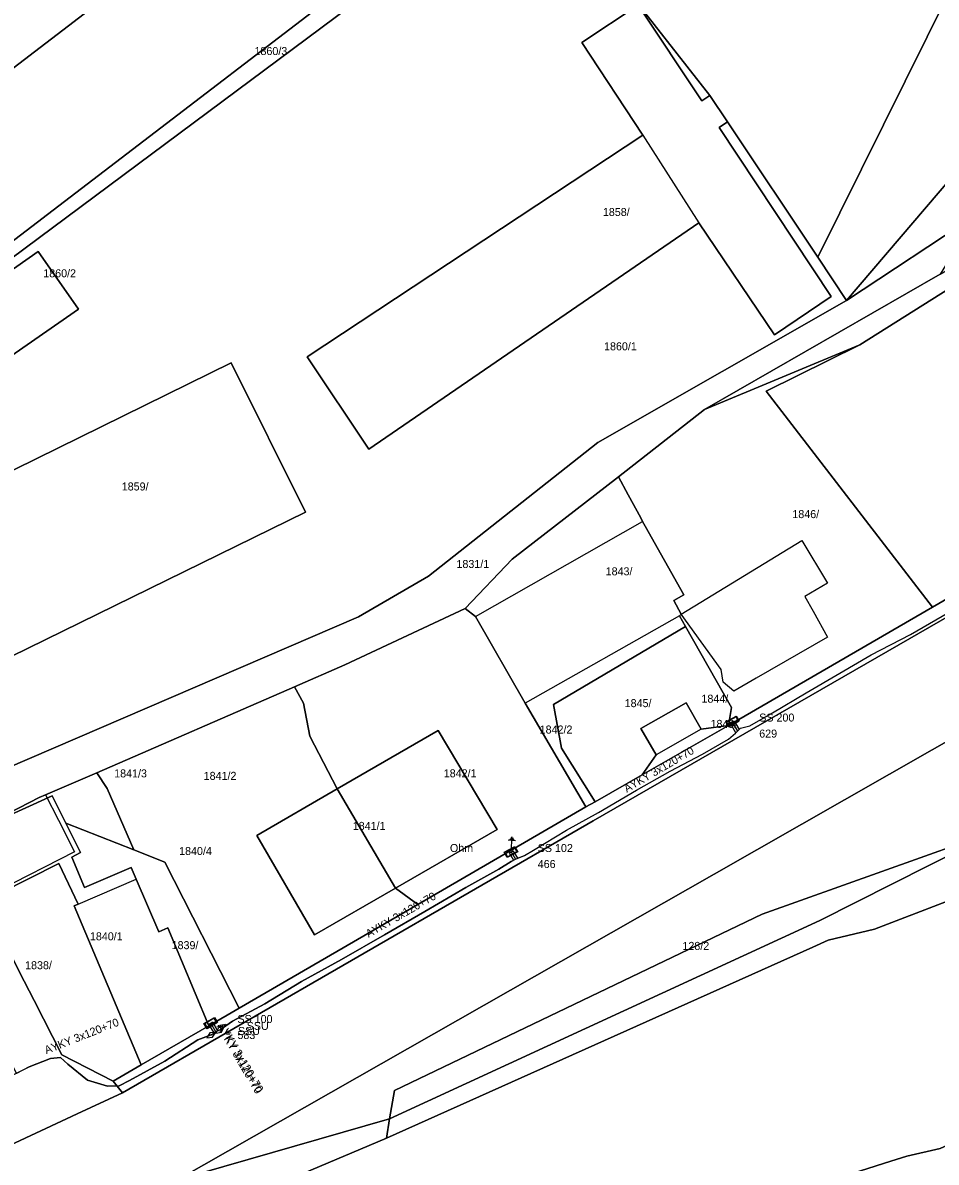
# Model space of a CAD drawing. Extents: x -793400 to -756198, y -1074141 to -1042963.
# Drawn here: x -783672.6 to -783587.1, y -1065150.4 to -1065043.7 of the extents above; entities that cross this region are included whole.
import ezdxf

# ---------------------------------------------------------------- set-up
doc = ezdxf.new("R2010")
doc.units = 0
for name, color, linetype in [('Parcela', 7, 'Continuous'), ('Popiskový text - Parcela', 7, 'Continuous'), ('Popiskový text - Přípojková skříň nn - SJZ', 7, 'Continuous'), ('Popiskový text - Přípojková skříň nn - Typ', 7, 'Continuous'), ('Popiskový text - Spojka nn - Typ', 7, 'Continuous'), ('Popiskový text - Uzemnění - Odpor', 7, 'Continuous'), ('Popiskový text - Vedení nn kabelové', 7, 'Continuous'), ('Skříň', 7, 'Continuous'), ('Spojka nn', 7, 'Continuous'), ('Spojnice nn', 7, 'Continuous'), ('Stavební objekt', 7, 'Continuous'), ('Uzemnění', 7, 'Continuous'), ('Vedení nn kabelové', 7, 'Continuous')]:
    doc.layers.add(name, color=color, linetype=linetype)

msp = doc.modelspace()

# ---------------------------------------------------------------- linework, layer by layer
at = {"layer": 'Parcela'}
for points in [[(-783679.68, -1065165.57), (-783638.54, -1065148.19), (-783598.62, -1065130.29), (-783597.17, -1065129.64), (-783592.85, -1065128.61), (-783579.36, -1065123.41), (-783559.97, -1065115.54), (-783529.78, -1065097.96), (-783514.83, -1065080.59), (-783511.59, -1065076.83), (-783504.59, -1065066.42), (-783502.44, -1065059.14), (-783500.79, -1065053.34), (-783499.02, -1065044.63), (-783497.17, -1065032.71), (-783496.04, -1065023.77), (-783495.21, -1065016.12), (-783492.53, -1064987.86), (-783488.71, -1064964.21), (-783486.09, -1064952.5), (-783482.83, -1064940.99), (-783478.28, -1064929.62)], [(-783478.28, -1064929.62), (-783482.83, -1064940.99), (-783486.09, -1064952.5), (-783488.71, -1064964.21), (-783492.53, -1064987.86), (-783497.09, -1065007.24), (-783502.14, -1065032.55), (-783506.35, -1065048.95), (-783511.77, -1065063.08), (-783521.44, -1065073.34), (-783546.39, -1065088.37), (-783607.85, -1065123.43), (-783658.1, -1065152.09), (-783678.31, -1065163.62)], [(-783676.21, -1065149.95), (-783668.48, -1065146.36), (-783667.48, -1065145.9), (-783663.26, -1065143.94), (-783619.19, -1065118.45), (-783559.07, -1065083.82), (-783559.84, -1065082.45), (-783540.15, -1065071.29), (-783534.17, -1065067.9), (-783529.45, -1065065.23), (-783521.94, -1065058.84), (-783520.86, -1065057.92), (-783514.53, -1065031.25), (-783497.32, -1064954.63), (-783495.09, -1064947.27), (-783490, -1064932.55)], [(-783461.55, -1064937.01), (-783469.34, -1064952.28), (-783475.47, -1064981.45), (-783479.58, -1065017.78), (-783482.56, -1065054.25), (-783487.35, -1065074.33), (-783494.31, -1065088.74), (-783495.21, -1065089.71), (-783498.48, -1065093.26), (-783502.16, -1065097.24), (-783520.29, -1065114.03), (-783532.97, -1065123.26), (-783564.78, -1065139.29), (-783586.68, -1065149.16), (-783589.8, -1065149.85), (-783591.32, -1065150.33), (-783630.75, -1065162.93), (-783655.71, -1065172.17), (-783680.17, -1065182.98)], [(-783680.17, -1065182.98), (-783655.71, -1065172.17), (-783630.75, -1065162.93), (-783591.32, -1065150.33), (-783589.8, -1065149.85), (-783586.68, -1065149.16), (-783564.78, -1065139.29), (-783532.97, -1065123.26), (-783520.29, -1065114.03), (-783502.16, -1065097.24), (-783498.48, -1065093.26), (-783495.21, -1065089.71), (-783494.31, -1065088.74), (-783487.35, -1065074.33), (-783482.56, -1065054.25), (-783479.58, -1065017.78), (-783475.47, -1064981.45), (-783469.34, -1064952.28), (-783461.55, -1064937.01)], [(-783497.17, -1065032.71), (-783499.02, -1065044.63), (-783500.79, -1065053.34), (-783502.44, -1065059.14), (-783504.59, -1065066.42), (-783512.37, -1065073.74), (-783513.55, -1065075.3), (-783516.49, -1065079.31), (-783531.67, -1065094.68), (-783561.96, -1065112.08), (-783580.95, -1065119.21), (-783603.34, -1065127.19), (-783637.77, -1065143.7), (-783638.24, -1065146.37), (-783658.1, -1065152.09), (-783607.85, -1065123.43), (-783546.39, -1065088.37), (-783521.44, -1065073.34), (-783511.77, -1065063.08), (-783506.35, -1065048.95), (-783502.14, -1065032.55)], [(-783680.77, -1065116.4), (-783641.16, -1065099.33), (-783634.61, -1065095.52), (-783618.75, -1065083), (-783595.45, -1065069.7), (-783583.27, -1065061.66), (-783586.7, -1065067.25), (-783608.77, -1065079.92), (-783616.82, -1065086.21), (-783626.75, -1065093.93), (-783631.18, -1065098.55), (-783642.42, -1065103.85), (-783647.16, -1065105.91), (-783665.66, -1065113.94), (-783670.46, -1065116.02), (-783671.05, -1065116.27), (-783677.6, -1065119.63)]]:
    msp.add_lwpolyline(points, dxfattribs=at)
for points in [[(-783679.72, -1065068.87), (-783696.3, -1065082.59), (-783703.49, -1065067.95), (-783701.82, -1065066.6), (-783693.07, -1065059.53), (-783681.16, -1065034.03), (-783688.84, -1065024.56), (-783667.93, -1064997.88), (-783659.12, -1064988.88), (-783657.73, -1064987.44), (-783656.18, -1064989.41), (-783657.28, -1064990.53), (-783648.71, -1064998.93), (-783633.99, -1065017.67), (-783634.29, -1065017.9), (-783683.34, -1065055.48), (-783678.2, -1065062.3), (-783682.41, -1065065.47)], [(-783594.2, -1065073.85), (-783608.77, -1065079.92), (-783586.7, -1065067.25), (-783573.68, -1065059.58), (-783565.81, -1065041.46), (-783556.5, -1065031.75), (-783555.01, -1065019.55), (-783544.22, -1064989.94), (-783545.48, -1065011.72), (-783554.46, -1065031.61), (-783557.75, -1065043.78), (-783560.55, -1065049.48), (-783561.45, -1065051.31), (-783563.64, -1065054.8), (-783565.28, -1065056.42), (-783566.79, -1065057.9), (-783570.36, -1065060.29), (-783572.51, -1065061.34), (-783577.12, -1065063.08)], [(-783575.44, -1065003.73), (-783565.51, -1065017.86), (-783567.73, -1065031.83), (-783572.73, -1065039.92), (-783583.05, -1065055.14), (-783595.45, -1065069.7), (-783598.14, -1065065.66), (-783579.73, -1065028.49), (-783592.56, -1065011.81), (-783602.84, -1065017.41), (-783606.12, -1065012.66), (-783597.36, -1065006.04), (-783592.12, -1065001.98), (-783590.3, -1065000.59)], [(-783579.73, -1065028.49), (-783598.14, -1065065.66), (-783606.59, -1065052.98), (-783608.24, -1065050.49), (-783624.81, -1065029.37), (-783602.84, -1065017.41), (-783592.56, -1065011.81)], [(-783626.47, -1065028.12), (-783679.72, -1065068.87), (-783682.41, -1065065.47), (-783678.2, -1065062.3), (-783683.34, -1065055.48), (-783634.29, -1065017.9), (-783633.99, -1065017.67), (-783626.05, -1065027.79)], [(-783583.27, -1065061.66), (-783595.45, -1065069.7), (-783583.05, -1065055.14), (-783572.73, -1065039.92), (-783567.73, -1065031.83), (-783565.51, -1065017.86), (-783562.68, -1065021.88), (-783563.99, -1065030.67), (-783581.17, -1065058.24)], [(-783624.81, -1065029.37), (-783696.3, -1065082.59), (-783679.72, -1065068.87), (-783626.47, -1065028.12), (-783626.05, -1065027.79)], [(-783624.81, -1065029.37), (-783608.24, -1065050.49), (-783609.02, -1065051.01), (-783614.97, -1065042.05), (-783620.25, -1065045.55), (-783614.53, -1065054.22), (-783645.96, -1065074.99), (-783640.19, -1065083.64), (-783609.28, -1065062.42), (-783602.2, -1065072.93), (-783596.89, -1065069.32), (-783607.37, -1065053.5), (-783606.59, -1065052.98), (-783598.14, -1065065.66), (-783595.45, -1065069.7), (-783618.75, -1065083), (-783634.61, -1065095.52), (-783641.16, -1065099.33), (-783680.77, -1065116.4), (-783687.19, -1065102.12), (-783688.13, -1065100.02), (-783693.78, -1065087.45), (-783696.3, -1065082.59)], [(-783614.97, -1065042.05), (-783609.02, -1065051.01), (-783608.24, -1065050.49), (-783606.59, -1065052.98), (-783607.37, -1065053.5), (-783596.89, -1065069.32), (-783602.2, -1065072.93), (-783609.28, -1065062.42), (-783640.19, -1065083.64), (-783645.96, -1065074.99), (-783614.53, -1065054.22), (-783620.25, -1065045.55)], [(-783559.84, -1065082.45), (-783587.42, -1065098.44), (-783602.99, -1065078.19), (-783594.2, -1065073.85), (-783577.12, -1065063.08), (-783572.51, -1065061.34)], [(-783667.38, -1065070.51), (-783671.15, -1065065.12), (-783678.96, -1065070.57), (-783675.18, -1065075.93)], [(-783667.38, -1065070.51), (-783675.18, -1065075.93), (-783678.96, -1065070.57), (-783671.15, -1065065.12)], [(-783598.62, -1065130.29), (-783638.54, -1065148.19), (-783638.24, -1065146.37), (-783597.95, -1065127.79), (-783580.95, -1065119.21), (-783561.96, -1065112.08), (-783531.67, -1065094.68), (-783516.49, -1065079.31), (-783513.55, -1065075.3), (-783512.37, -1065073.74), (-783504.59, -1065066.42), (-783511.59, -1065076.83), (-783514.83, -1065080.59), (-783529.78, -1065097.96), (-783559.97, -1065115.54), (-783579.36, -1065123.41), (-783592.85, -1065128.61), (-783597.17, -1065129.64)], [(-783587.42, -1065098.44), (-783606.5, -1065109.51), (-783606.24, -1065107.84), (-783610.53, -1065100.23), (-783611.09, -1065099.25), (-783610.93, -1065099.1), (-783611.64, -1065097.81), (-783610.68, -1065097.28), (-783614.3, -1065090.84), (-783614.55, -1065090.41), (-783614.73, -1065090.07), (-783615.91, -1065087.92), (-783616.82, -1065086.21), (-783608.77, -1065079.92), (-783594.2, -1065073.85), (-783602.99, -1065078.19)], [(-783646.12, -1065089.53), (-783653.08, -1065075.54), (-783685.51, -1065091.5), (-783678.6, -1065105.46)], [(-783646.12, -1065089.53), (-783678.6, -1065105.46), (-783685.51, -1065091.5), (-783653.08, -1065075.54)], [(-783619.19, -1065118.45), (-783663.26, -1065143.94), (-783664.13, -1065142.85), (-783661.5, -1065141.32), (-783655.16, -1065137.64), (-783652.34, -1065136), (-783635.6, -1065126.28), (-783619.86, -1065117.15), (-783619, -1065116.66), (-783614.6, -1065114.14), (-783606.5, -1065109.51), (-783587.42, -1065098.44), (-783559.84, -1065082.45), (-783559.07, -1065083.82)], [(-783619, -1065116.66), (-783619.86, -1065117.15), (-783625.54, -1065107.42), (-783630.2, -1065099.32), (-783631.18, -1065098.55), (-783626.75, -1065093.93), (-783616.82, -1065086.21), (-783615.91, -1065087.92), (-783614.73, -1065090.07), (-783614.55, -1065090.41), (-783614.3, -1065090.84), (-783610.68, -1065097.28), (-783611.64, -1065097.81), (-783610.93, -1065099.1), (-783611.09, -1065099.25), (-783610.53, -1065100.23), (-783622.9, -1065107.55), (-783622.14, -1065111.63)], [(-783625.54, -1065107.42), (-783619.86, -1065117.15), (-783635.6, -1065126.28), (-783637.69, -1065124.76), (-783628.16, -1065119.27), (-783633.69, -1065109.98), (-783643.15, -1065115.45), (-783645.7, -1065110.51), (-783646.3, -1065107.44), (-783647.16, -1065105.91), (-783642.42, -1065103.85), (-783631.18, -1065098.55), (-783630.2, -1065099.32)], [(-783610.53, -1065100.23), (-783606.24, -1065107.84), (-783606.5, -1065109.51), (-783609.06, -1065109.87), (-783610.48, -1065107.38), (-783614.71, -1065109.8), (-783613.28, -1065112.27), (-783614.6, -1065114.14), (-783619, -1065116.66), (-783622.14, -1065111.63), (-783622.9, -1065107.55)], [(-783650.67, -1065119.81), (-783645.28, -1065129.14), (-783637.69, -1065124.76), (-783635.6, -1065126.28), (-783652.34, -1065136), (-783659.28, -1065122.31), (-783662.2, -1065121.16), (-783664.69, -1065115.43), (-783665.66, -1065113.94), (-783647.16, -1065105.91), (-783646.3, -1065107.44), (-783645.7, -1065110.51), (-783643.15, -1065115.45)], [(-783610.48, -1065107.38), (-783609.06, -1065109.87), (-783606.5, -1065109.51), (-783614.6, -1065114.14), (-783613.28, -1065112.27), (-783614.71, -1065109.8)], [(-783628.16, -1065119.27), (-783637.69, -1065124.76), (-783643.15, -1065115.45), (-783633.69, -1065109.98)], [(-783664.69, -1065115.43), (-783662.2, -1065121.16), (-783668.56, -1065118.67), (-783669.82, -1065116.11), (-783677.6, -1065119.63), (-783671.05, -1065116.27), (-783670.46, -1065116.02), (-783665.66, -1065113.94)], [(-783668, -1065121.84), (-783666.8, -1065124.7), (-783662.43, -1065122.81), (-783661.97, -1065123.9), (-783659.86, -1065128.84), (-783658.99, -1065128.48), (-783655.16, -1065137.64), (-783661.5, -1065141.32), (-783667.76, -1065126.41), (-783667.4, -1065126.25), (-783669.21, -1065122.45), (-783674.74, -1065125.24), (-783674.87, -1065124.98), (-783676.39, -1065125.75), (-783679.11, -1065120.41), (-783677.6, -1065119.63), (-783669.82, -1065116.11), (-783668.56, -1065118.67), (-783667.19, -1065121.43)], [(-783637.69, -1065124.76), (-783645.28, -1065129.14), (-783650.67, -1065119.81), (-783643.15, -1065115.45)], [(-783659.28, -1065122.31), (-783652.34, -1065136), (-783655.16, -1065137.64), (-783658.99, -1065128.48), (-783659.86, -1065128.84), (-783661.97, -1065123.9), (-783662.43, -1065122.81), (-783666.8, -1065124.7), (-783668, -1065121.84), (-783667.19, -1065121.43), (-783668.56, -1065118.67), (-783662.2, -1065121.16)], [(-783597.95, -1065127.79), (-783638.24, -1065146.37), (-783637.77, -1065143.7), (-783603.34, -1065127.19), (-783580.95, -1065119.21)], [(-783668.48, -1065146.36), (-783676.21, -1065149.95), (-783674.25, -1065143), (-783683.17, -1065125.09), (-783684.71, -1065122), (-783681.3, -1065120.7), (-783679.42, -1065119.99), (-783679.34, -1065119.96), (-783679.11, -1065120.41), (-783676.39, -1065125.75), (-783672.45, -1065133.46), (-783671.53, -1065135.28), (-783668.93, -1065140.36), (-783664.13, -1065142.85), (-783663.26, -1065143.94), (-783667.48, -1065145.9)], [(-783669.21, -1065122.45), (-783667.4, -1065126.25), (-783667.76, -1065126.41), (-783661.5, -1065141.32), (-783664.13, -1065142.85), (-783668.93, -1065140.36), (-783671.53, -1065135.28), (-783672.45, -1065133.46), (-783676.39, -1065125.75), (-783674.87, -1065124.98), (-783674.74, -1065125.24)], [(-783638.54, -1065148.19), (-783679.68, -1065165.57), (-783678.31, -1065163.62), (-783658.1, -1065152.09), (-783638.24, -1065146.37)]]:
    msp.add_lwpolyline(points, close=True, dxfattribs=at)
at = {"layer": 'Skříň'}
for points in [[(-783606.76, -1065109.18), (-783605.78, -1065108.63), (-783605.5, -1065109.12), (-783606.48, -1065109.67)], [(-783605.8, -1065108.71), (-783606.68, -1065109.2), (-783606.46, -1065109.59), (-783605.58, -1065109.1)], [(-783627.5, -1065121.39), (-783626.51, -1065120.86), (-783626.24, -1065121.35), (-783627.23, -1065121.88)], [(-783626.53, -1065120.93), (-783627.42, -1065121.41), (-783627.21, -1065121.81), (-783626.32, -1065121.33)], [(-783655.62, -1065137.44), (-783654.65, -1065136.86), (-783654.36, -1065137.34), (-783655.33, -1065137.92)], [(-783654.67, -1065136.94), (-783655.54, -1065137.46), (-783655.31, -1065137.84), (-783654.44, -1065137.32)]]:
    msp.add_lwpolyline(points, close=True, dxfattribs=at)
at = {"layer": 'Spojka nn'}
for points in [[(-783653.72, -1065137.74), (-783654.27, -1065137.84), (-783654.52, -1065138.33), (-783653.97, -1065138.24)], [(-783654.52, -1065138.24), (-783655.07, -1065138.3), (-783655.36, -1065138.78), (-783654.81, -1065138.72)]]:
    msp.add_lwpolyline(points, close=True, dxfattribs=at)
at = {"layer": 'Spojnice nn'}
for p, q in [((-783654.51, -1065138.22), (-783654.99, -1065137.39)), ((-783654.94, -1065138.51), (-783654.51, -1065138.22)), ((-783654.12, -1065138.04), (-783654.51, -1065138.22))]:
    msp.add_line(p, q, dxfattribs=at)
for points in [[(-783605.66, -1065110.04), (-783605.37, -1065109.78), (-783604.52, -1065109.54), (-783602.4, -1065108.33), (-783599.24, -1065106.46), (-783596.07, -1065104.6), (-783593.16, -1065102.89), (-783589.48, -1065101), (-783585.9, -1065098.93), (-783582.6, -1065097.1), (-783579.01, -1065094.9), (-783575.84, -1065093.11), (-783573.09, -1065091.68), (-783569.76, -1065089.62)], [(-783626.45, -1065122.03), (-783625.6, -1065121.71), (-783624.76, -1065121.21), (-783621.67, -1065119.33), (-783618.69, -1065117.66), (-783615.12, -1065115.57), (-783611.96, -1065113.79), (-783608.95, -1065112.19), (-783606.51, -1065110.79), (-783605.86, -1065110.24), (-783605.66, -1065110.04)], [(-783606.13, -1065109.15), (-783606, -1065109.45), (-783605.66, -1065110.04)], [(-783626.87, -1065121.37), (-783626.71, -1065121.6), (-783626.45, -1065122.03)], [(-783654.12, -1065138.04), (-783652.94, -1065137.23), (-783649.93, -1065135.58), (-783646.48, -1065133.51), (-783642.73, -1065131.45), (-783638.73, -1065129.14), (-783634.94, -1065126.95), (-783631.09, -1065124.68), (-783628.02, -1065122.97), (-783626.87, -1065122.26), (-783626.45, -1065122.03)], [(-783673.55, -1065142.29), (-783671.98, -1065141.48), (-783670, -1065140.7), (-783669.05, -1065140.63), (-783668.38, -1065141.25), (-783666.53, -1065142.74), (-783664.64, -1065143.29), (-783663.56, -1065143.27), (-783662.58, -1065142.79), (-783659.29, -1065140.97), (-783656.19, -1065138.98), (-783654.94, -1065138.51)]]:
    msp.add_lwpolyline(points, dxfattribs=at)
at = {"layer": 'Stavební objekt'}
for points in [[(-783626.47, -1065028.12), (-783679.72, -1065068.87), (-783682.41, -1065065.47), (-783678.2, -1065062.3), (-783683.34, -1065055.48), (-783634.29, -1065017.9)], [(-783609.28, -1065062.42), (-783640.19, -1065083.64), (-783645.96, -1065074.99), (-783614.53, -1065054.22)], [(-783667.38, -1065070.51), (-783675.18, -1065075.93), (-783678.96, -1065070.57), (-783671.15, -1065065.12)], [(-783646.12, -1065089.53), (-783678.6, -1065105.46), (-783685.51, -1065091.5), (-783653.08, -1065075.54)], [(-783611.09, -1065099.25), (-783625.54, -1065107.42), (-783630.2, -1065099.32), (-783614.55, -1065090.41), (-783614.3, -1065090.84), (-783610.68, -1065097.28), (-783611.64, -1065097.81), (-783610.93, -1065099.1)], [(-783603.92, -1065105.08), (-783606.01, -1065106.3), (-783607, -1065105.47), (-783607.18, -1065104.27), (-783610.93, -1065099.1), (-783599.63, -1065092.18), (-783597.24, -1065096.19), (-783599.37, -1065097.42), (-783598.57, -1065098.8), (-783597.25, -1065101.25)], [(-783609.06, -1065109.87), (-783613.28, -1065112.27), (-783614.71, -1065109.8), (-783610.48, -1065107.38)], [(-783628.16, -1065119.27), (-783637.69, -1065124.76), (-783643.15, -1065115.45), (-783633.69, -1065109.98)], [(-783667.74, -1065121.34), (-783674.87, -1065124.98), (-783677.6, -1065119.63), (-783671.05, -1065116.27), (-783670.46, -1065116.02), (-783669.24, -1065118.4)], [(-783637.69, -1065124.76), (-783645.28, -1065129.14), (-783650.67, -1065119.81), (-783643.15, -1065115.45)], [(-783661.97, -1065123.9), (-783659.86, -1065128.84), (-783658.99, -1065128.48), (-783655.16, -1065137.64), (-783661.5, -1065141.32), (-783667.76, -1065126.41), (-783667.4, -1065126.25)]]:
    msp.add_lwpolyline(points, close=True, dxfattribs=at)
at = {"layer": 'Uzemnění'}
for p, q in [((-783626.45, -1065120.32), (-783627.14, -1065120.27)), ((-783626.57, -1065120.22), (-783627.01, -1065120.19)), ((-783626.64, -1065120.11), (-783626.93, -1065120.09)), ((-783626.84, -1065120.98), (-783626.8, -1065120.29)), ((-783626.73, -1065120), (-783626.83, -1065119.99))]:
    msp.add_line(p, q, dxfattribs=at)
at = {"layer": 'Vedení nn kabelové'}
for points in [[(-783606.13, -1065109.15), (-783605.95, -1065109.07), (-783605.82, -1065109.36), (-783605.51, -1065109.9), (-783605.37, -1065109.78), (-783604.52, -1065109.54), (-783602.4, -1065108.33), (-783599.24, -1065106.46), (-783596.07, -1065104.6), (-783593.16, -1065102.89), (-783589.48, -1065101), (-783585.9, -1065098.93), (-783582.6, -1065097.1), (-783579.01, -1065094.9), (-783575.84, -1065093.11), (-783573.09, -1065091.68), (-783569.67, -1065089.8), (-783567.99, -1065088.97), (-783567.05, -1065087.88), (-783566.93, -1065087.38), (-783566.93, -1065087.12)], [(-783626.87, -1065121.37), (-783626.71, -1065121.26), (-783626.54, -1065121.49), (-783626.26, -1065121.96), (-783625.6, -1065121.71), (-783624.76, -1065121.21), (-783621.67, -1065119.33), (-783618.69, -1065117.66), (-783615.12, -1065115.57), (-783611.96, -1065113.79), (-783608.95, -1065112.19), (-783606.51, -1065110.79), (-783605.86, -1065110.24), (-783605.81, -1065110.19), (-783606.18, -1065109.54), (-783606.31, -1065109.23), (-783606.13, -1065109.15)], [(-783626.87, -1065121.37), (-783627.03, -1065121.48), (-783626.88, -1065121.71), (-783626.63, -1065122.13), (-783626.87, -1065122.26), (-783628.02, -1065122.97), (-783631.09, -1065124.68), (-783634.94, -1065126.95), (-783638.73, -1065129.14), (-783642.73, -1065131.45), (-783646.48, -1065133.51), (-783649.93, -1065135.58), (-783652.94, -1065137.23), (-783654.12, -1065138.04)], [(-783654.94, -1065138.51), (-783656.19, -1065138.98), (-783659.29, -1065140.97), (-783662.58, -1065142.79), (-783663.56, -1065143.27), (-783664.64, -1065143.29), (-783666.53, -1065142.74), (-783668.38, -1065141.25), (-783669.05, -1065140.63), (-783670, -1065140.7), (-783671.98, -1065141.48), (-783673.19, -1065142.11), (-783676.67, -1065135.15), (-783677.44, -1065133.77), (-783678.4, -1065132.05), (-783678.6, -1065131.62), (-783679.38, -1065131.91), (-783679.66, -1065132.03), (-783679.88, -1065132.03), (-783679.88, -1065132.42), (-783679.58, -1065132.42), (-783679.58, -1065132.18)], [(-783654.94, -1065138.51), (-783654.68, -1065138.32), (-783655.16, -1065137.49), (-783654.99, -1065137.39)], [(-783654.99, -1065137.39), (-783654.82, -1065137.29), (-783654.34, -1065138.12), (-783654.12, -1065138.04)]]:
    msp.add_lwpolyline(points, dxfattribs=at)

# ---------------------------------------------------------------- texts
at = {"layer": 'Popiskový text - Parcela'}
for s, p in [('1860/3', (-783650.89, -1065046.71)), ('1858/', (-783618.27, -1065061.79)), ('1860/2', (-783670.67, -1065067.53)), ('1860/1', (-783618.16, -1065074.37)), ('1859/', (-783663.32, -1065087.5)), ('1846/', (-783600.53, -1065090.09)), ('1831/1', (-783631.98, -1065094.76)), ('1843/', (-783618.01, -1065095.45)), ('1844/', (-783609.04, -1065107.38)), ('1845/', (-783616.23, -1065107.8)), ('1849/', (-783608.19, -1065109.74)), ('1842/2', (-783624.19, -1065110.27)), ('1841/3', (-783664.03, -1065114.38)), ('1841/2', (-783655.65, -1065114.61)), ('1842/1', (-783633.17, -1065114.37)), ('1841/1', (-783641.69, -1065119.3)), ('1840/4', (-783657.95, -1065121.65)), ('1840/1', (-783666.3, -1065129.64)), ('1839/', (-783658.65, -1065130.47)), ('128/2', (-783610.82, -1065130.54)), ('1838/', (-783672.37, -1065132.35))]:
    msp.add_text(s, height=0.75, dxfattribs=at).set_placement(p)
at = {"layer": 'Popiskový text - Přípojková skříň nn - SJZ'}
for s, p in [('629', (-783603.63, -1065110.65)), ('466', (-783624.37, -1065122.87)), ('583', (-783652.49, -1065138.89))]:
    msp.add_text(s, height=0.75, dxfattribs=at).set_placement(p)
at = {"layer": 'Popiskový text - Přípojková skříň nn - Typ'}
for s, p in [('SS 200', (-783603.63, -1065109.15)), ('SS 102', (-783624.37, -1065121.37)), ('SS 100', (-783652.49, -1065137.39))]:
    msp.add_text(s, height=0.75, dxfattribs=at).set_placement(p)
at = {"layer": 'Popiskový text - Spojka nn - Typ'}
for p in [(-783652.44, -1065138.51), (-783651.62, -1065138.04)]:
    msp.add_text('SSU', height=0.75, dxfattribs=at).set_placement(p)
at = {"layer": 'Popiskový text - Uzemnění - Odpor'}
msp.add_text(' Ohm', height=0.75, dxfattribs=at).set_placement((-783632.87, -1065121.37))
at = {"layer": 'Popiskový text - Vedení nn kabelové'}
for rotation, p in [(30.3668, (-783616.03, -1065115.82)), (30.023, (-783640.21, -1065129.42)), (21.4859, (-783670.38, -1065140.31)), (300.058, (-783654.46, -1065137.71)), (300.058, (-783654.35, -1065137.59))]:
    msp.add_text('AYKY 3x120+70', height=0.75, rotation=rotation, dxfattribs=at).set_placement(p)

doc.saveas('drawing.dxf')
